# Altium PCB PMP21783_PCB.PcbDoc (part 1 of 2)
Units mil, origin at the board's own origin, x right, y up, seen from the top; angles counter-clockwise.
Board outline 4600 x 4035 mil, 2 copper layers (Top Layer, Bottom Layer), stack 62 mil thick; 142 components, 69 nets, 309 pads, 93 vias.
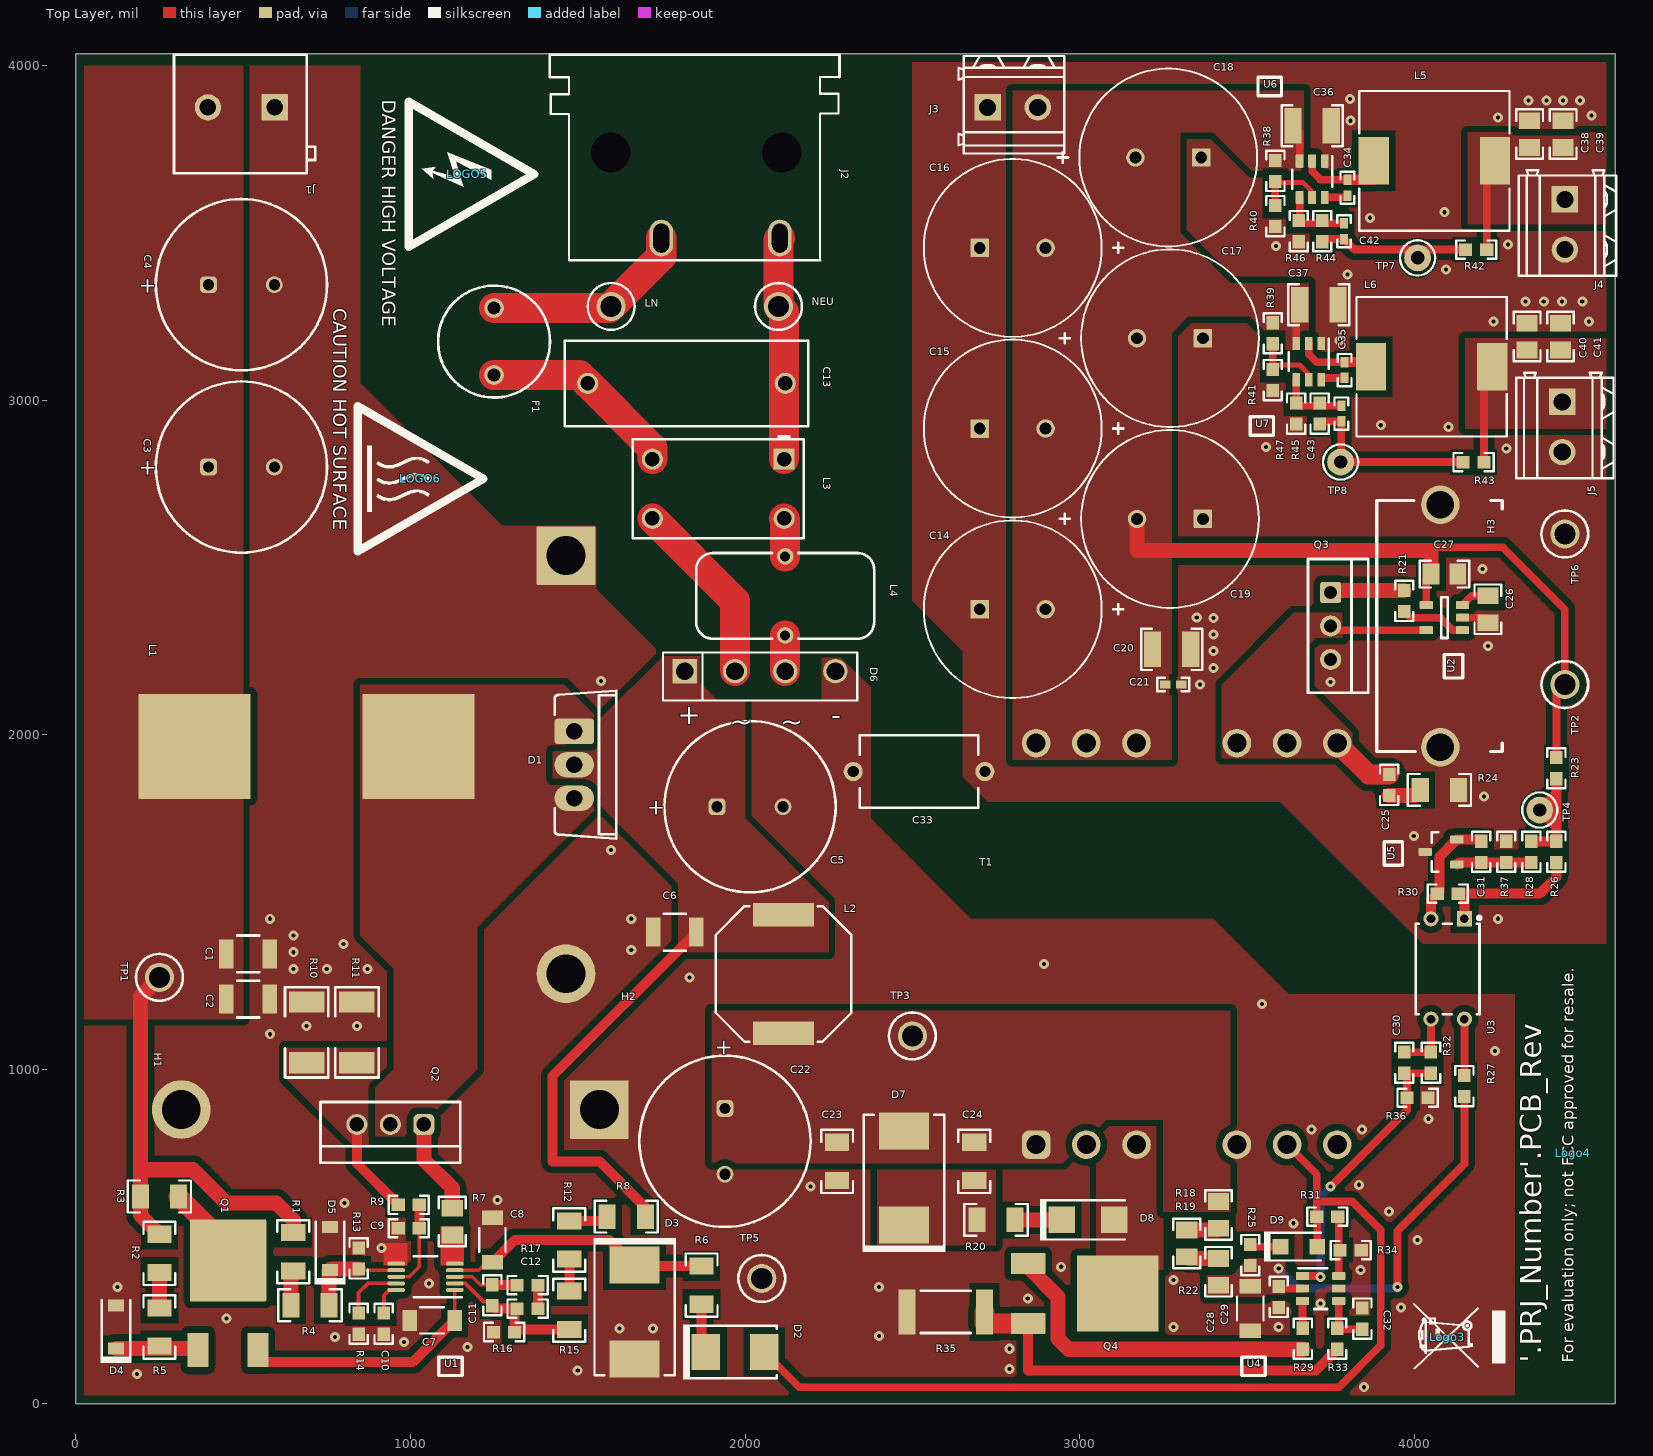
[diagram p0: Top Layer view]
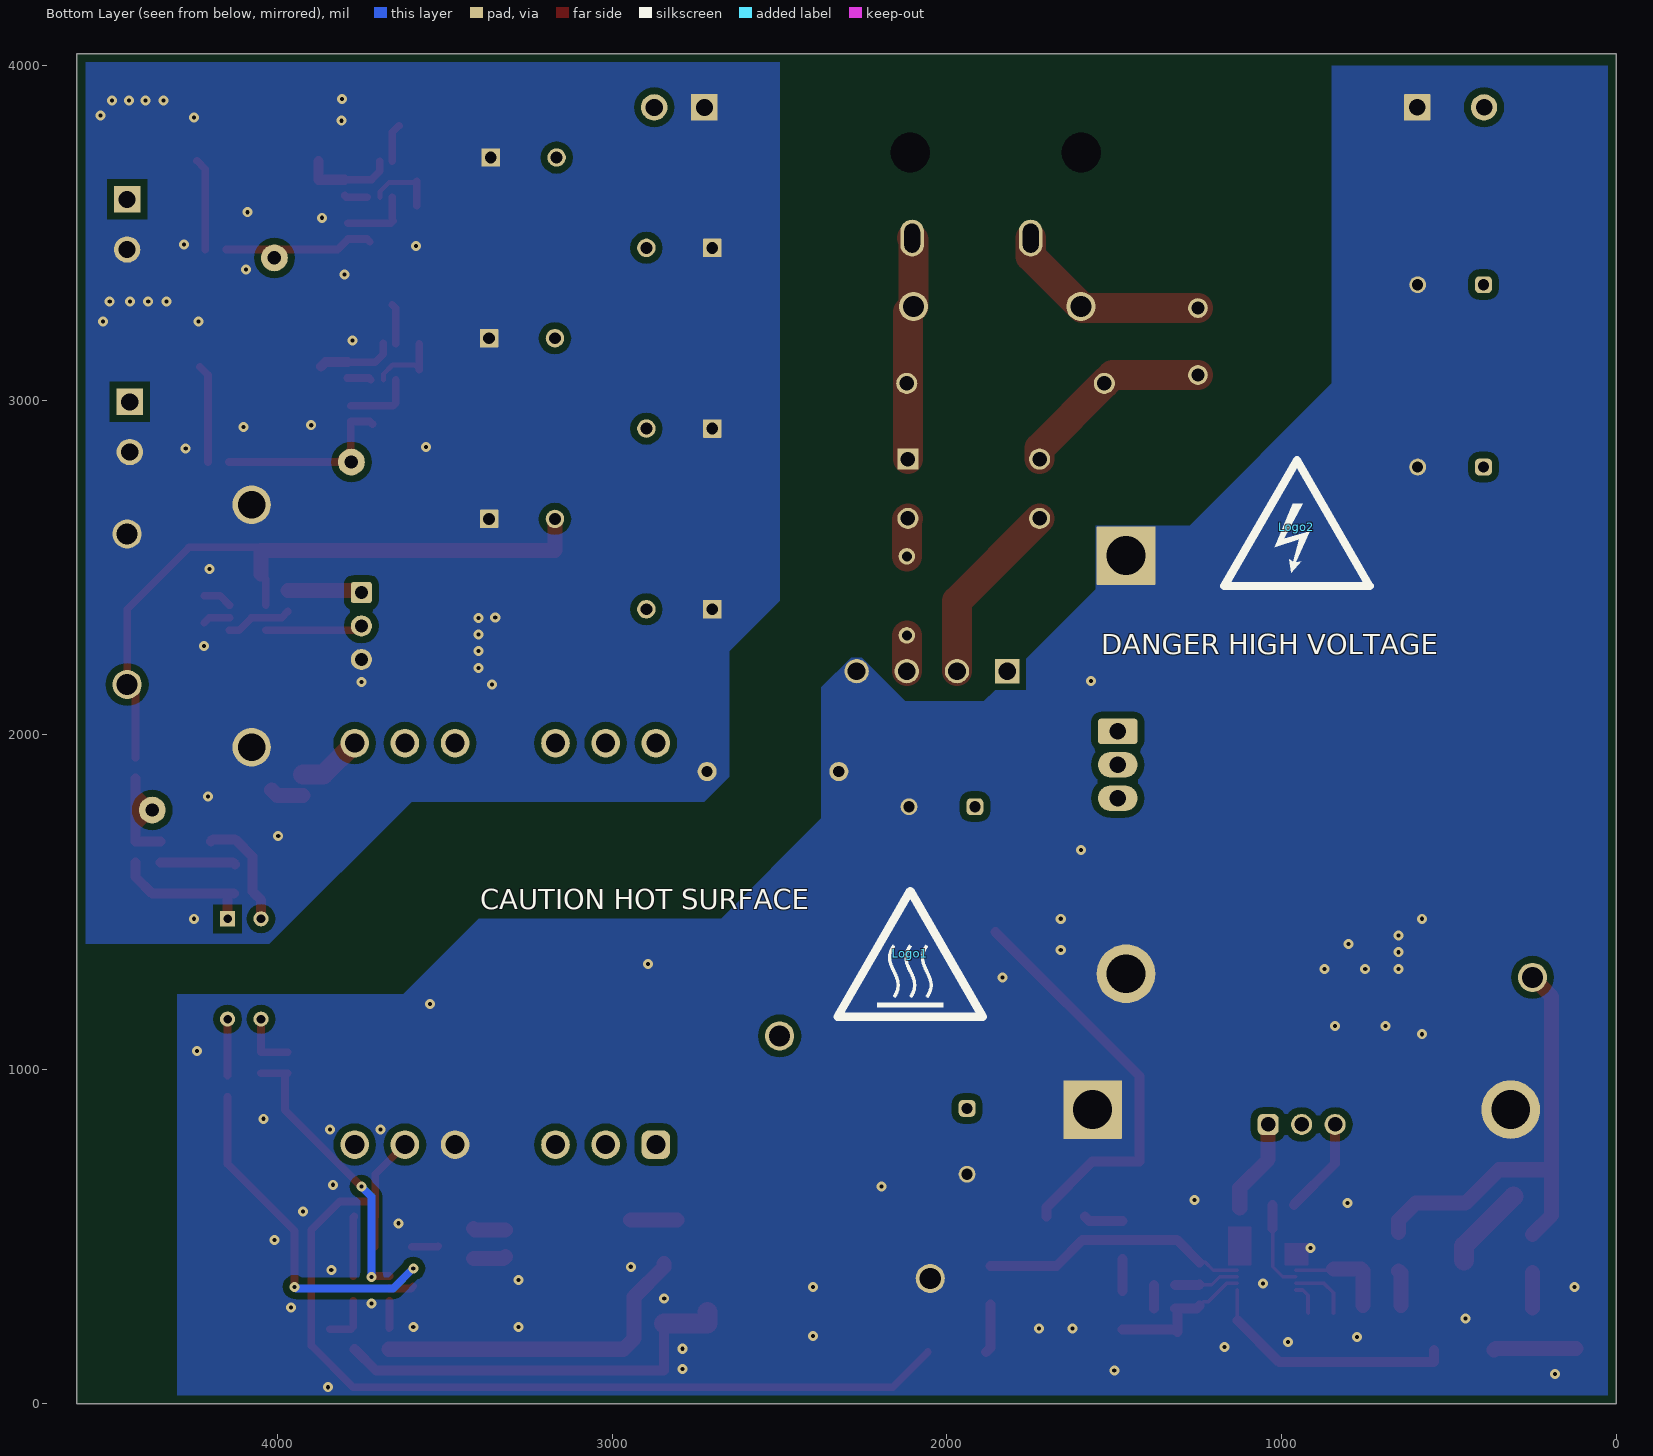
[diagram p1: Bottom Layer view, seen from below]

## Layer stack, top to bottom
Top Solder: solder mask 0.4, Solder Resist, Dk 3.5
Top Layer: signal copper 1.4
Dielectric1: core 59.2, FR-4, Dk 4.8
Bottom Layer: signal copper 1.4
Bottom Solder: solder mask 0.4, Solder Resist, Dk 3.5

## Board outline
0,0 4600,0 4600,4035 0,4035

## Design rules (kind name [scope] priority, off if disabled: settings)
AcuteAngle [All] p1: minimum=4.50000000000000E+0001 checktracksonly=FALSE
AssemblyTestPointUsage [All] p1: valid=2
BoardOutlineClearance BoardOutlineClearance_MountingHoles [OnCopper and InComponentClass('Mounting Holes')] p1: gap=25 ignorepadtopadclearanceinfootprint=FALSE
BoardOutlineClearance BoardOutlineClearance_Poly [OnCopper and InPoly] p2: gap=25 ignorepadtopadclearanceinfootprint=FALSE
BoardOutlineClearance [OnCopper and Not InComponentClass('Logo') and not InComponentClass('FiducialMark') and not InRegion(1000,500,4000,800)] p3: gap=25 ignorepadtopadclearanceinfootprint=FALSE
Clearance Clearance_2 [InNetClass('HV') vs Not InNetClass('HV')] p1: gap=60 ignorepadtopadclearanceinfootprint=FALSE
Clearance Clearance_1 [InNetClass('MV') vs Not InNetClass('MV')] p2: gap=30 ignorepadtopadclearanceinfootprint=FALSE
Clearance Clearance_Keepouts [((IsTrack Or IsArc) And Not InPoly) And IsFree and IsKeepOut vs ((IsTrack Or IsArc) And Not InPoly) And IsFree and IsKeepOut] p3: gap=0 ignorepadtopadclearanceinfootprint=FALSE
Clearance Clearance_BoardEdge_MountingHoles [OnCopper and InComponentClass('Mounting Holes') vs IsKeepOut] p4: gap=40 ignorepadtopadclearanceinfootprint=FALSE except(0: Arc-Hole Track-Hole SMDPad-Hole THPad-Hole Via-Hole Fill-Hole Poly-Hole Region-Hole Text-Hole)
Clearance Clearance_BoardEdge_Poly [OnCopper and InPoly vs IsKeepOut] p5: gap=50 ignorepadtopadclearanceinfootprint=FALSE except(0: Arc-Hole Track-Hole SMDPad-Hole THPad-Hole Via-Hole Fill-Hole Poly-Hole Region-Hole Text-Hole)
Clearance Clearance_BoardEdge [OnCopper and Not InComponentClass('Logo') and not InComponentClass('FiducialMark') and not InRegion(1000,500,4000,800) and Not IsKeepout vs IsKeepOut] p6: gap=50 ignorepadtopadclearanceinfootprint=FALSE
Clearance Clearance_Poly [InPolygon] p7: gap=20 ignorepadtopadclearanceinfootprint=FALSE except(0: Arc-Hole Track-Hole SMDPad-Hole THPad-Hole Via-Hole Fill-Hole Poly-Hole Region-Hole Text-Hole)
Clearance [All] p8: gap=7.87 ignorepadtopadclearanceinfootprint=FALSE except(0: Arc-Hole Track-Hole SMDPad-Hole THPad-Hole Via-Hole Fill-Hole Poly-Hole Region-Hole Text-Hole)
ComponentClearance ComponentClearance_MountingHoles_FiducialMarks [InComponentClass('Mounting Holes') vs InComponentClass('FiducialMark')] p1: gap=20 collisioncheckmode=3 verticalgap=10 showdistances=FALSE
ComponentClearance ComponentClearance_Shunt [InComponentClass('Header') vs InComponentClass('Shunt')] p2: gap=0 collisioncheckmode=3 verticalgap=0 showdistances=FALSE
ComponentClearance ComponentClearance_Logo [InComponentClass('Logo')] p3: gap=5 collisioncheckmode=3 verticalgap=10 showdistances=FALSE
ComponentClearance ComponentClearance_ScrewToNut [(HasFootprint('NY PMS 440 0025 PH')) vs (HasFootprint('Keystone_1902C'))] p4: gap=20 collisioncheckmode=3 verticalgap=100000 showdistances=FALSE
ComponentClearance ComponentClearance_MountingHoles [InComponentClass('Mounting Holes')] p5: gap=20 collisioncheckmode=3 verticalgap=10 showdistances=FALSE
ComponentClearance ComponentClearance_SmallPassives [HasFootprint('0201*') or HasFootprint('0402*') or HasFootprint('0508') or HasFootprint('0603*') or HasFootprint('0612') or HasFootprint('0805*') or HasFootprint('0815*') or HasFootprint('0830*') or HasFootprint('1206*') or HasFootprint('1210*') or HasFootprint('1808*') or HasFootprint('1812*') or HasFootprint('1825*') or HasFootprint('2010*') or HasFootprint('2220*') or HasFootprint('2225*') or HasFootprint('2512*') or HasFootprint('2728*') or HasFootprint('3518*') vs HasFootprint('0201*') or HasFootprint('0402*') or HasFootprint('0508') or HasFootprint('0603*') or HasFootprint('0612') or HasFootprint('0805*') or HasFootprint('0815*') or HasFootprint('0830*') or HasFootprint('1206*') or HasFootprint('1210*') or HasFootprint('1808*') or HasFootprint('1812*') or HasFootprint('1825*') or HasFootprint('2010*') or HasFootprint('2220*') or HasFootprint('2225*') or HasFootprint('2512*') or HasFootprint('2728*') or HasFootprint('3518*')] p6: gap=20 collisioncheckmode=3 verticalgap=20 showdistances=FALSE
ComponentClearance ComponentClearance_THtoSMT [IsThruComponent vs IsSMTComponent] p7: gap=10 collisioncheckmode=3 verticalgap=10 showdistances=FALSE
ComponentClearance ComponentClearance_THtoTH [IsThruComponent vs IsThruComponent] p8: gap=10 collisioncheckmode=3 verticalgap=10 showdistances=FALSE
ComponentClearance [All] p9: gap=10 collisioncheckmode=3 verticalgap=10 showdistances=FALSE
DiffPairsRouting [All] p1: maxlimit=100 minlimit=10 mostfreqgap=10 toplayer_minwidth=15 toplayer_maxwidth=15 toplayer_prefwidth=15 bottomlayer_minwidth=15 bottomlayer_maxwidth=15 bottomlayer_prefwidth=15 maxuncoupledlength=1000
FabricationTestPointUsage TestPointUsage [All] p1: valid=2 allowmultiple=FALSE
FabricationTestpoint Testpoint [All] p1: side=3 testpointundercomponent=TRUE minsize=40 maxsize=100 preferedsize=60 minholesize=0 maxholesize=40 preferedholesize=32 testpointgrid=1 allowsidetop=TRUE allowsidebottom=TRUE usegrid=TRUE gridtolerance=0.01
FanoutControl Fanout_LCC [IsLCC] p1: bgadir=Out bgaviamode=Centered fanoutstyle=Auto fanoutdirection=Alternating viagrid=1 // Fanout_LCC (Default Rule)
FanoutControl Fanout_BGA [IsBGA] p2: bgadir=Out bgaviamode=Centered fanoutstyle=Auto fanoutdirection=Alternating viagrid=1 // Fanout_BGA (Default Rule)
FanoutControl Fanout_Default [All] p4: bgadir=Out bgaviamode=Centered fanoutstyle=Auto fanoutdirection=Alternating viagrid=1 // Fanout_Default (Default Rule)
FanoutControl Fanout_Small [(CompPinCount < 5)] p5: bgadir=Out bgaviamode=Centered fanoutstyle=Auto fanoutdirection=OutThenIn viagrid=1 // Fanout_Small (Default Rule)
Height [All] p1: minheight=0 maxheight=3000 prefheight=500
HoleSize [All] p1: absolutevalues=TRUE maxlimit=251 minlimit=7.87 maxpercent=80.000 minpercent=20.000
MinimumAnnularRing MinimumAnnularRing_ThermalPadVias [IsVia and InAnyComponent] p1: minimumring=5.91
MinimumAnnularRing [All] p2: minimumring=8
MinimumSolderMaskSliver MinimumSolderMaskSliver_Logo [InComponentClass('Logo') vs InComponentClass('Logo')] p1: minsoldermaskwidth=0.7
MinimumSolderMaskSliver [All] p2: minsoldermaskwidth=3.94
PlaneConnect [All] p1: planeconnectstyle=Direct reliefexpansion=10 reliefentries=4 reliefconductorwidth=10 reliefairgap=10
PolygonConnect PolygonConnect_15 [All vs IsNamedPolygon('C109_2') Or  IsNamedPolygon('C107_2') Or  IsNamedPolygon('HV') Or  IsNamedPolygon('Q203_5') Or  IsNamedPolygon('C107_2') Or  IsNamedPolygon('HS') Or  IsNamedPolygon('Q201_5') Or  IsNamedPolygon('Q203_5') Or  IsNamedPolygon('C106_2') Or  IsNamedPolygon('C108_2') Or  IsNamedPolygon('Vout') Or  IsNamedPolygon('Q203_5') Or  IsNamedPolygon('C108_2') Or  IsNamedPolygon('C113_2') Or  IsNamedPolygon('Q203_5') Or  IsNamedPolygon('Q201_5') Or  IsNamedPolygon('C107_2') Or  IsNamedPolygon('C102_1') Or  IsNamedPolygon('SGND') Or  IsNamedPolygon('GND') Or  IsNamedPolygon('SGND') Or  IsNamedPolygon('GND') Or  IsNamedPolygon('IN+') Or  IsNamedPolygon('IN+') Or  IsNamedPolygon('Q201_5') Or  IsNamedPolygon('Q201_5') Or  IsNamedPolygon('SGND') Or  IsNamedPolygon('SGND') Or  IsNamedPolygon('Vout') Or  IsNamedPolygon('Vout') Or  IsNamedPolygon('IN+') Or  IsNamedPolygon('GND') Or  IsNamedPolygon('IN+') Or  IsNamedPolygon('GND')] p1: connectstyle=Direct reliefconductorwidth=10 reliefentries=4 polygonreliefangle="90 Angle" airgapwidth=10
PolygonConnect PolygonConnect_14 [All vs IsNamedPolygon('C106_2') Or  IsNamedPolygon('C107_2') Or  IsNamedPolygon('C107_2') Or  IsNamedPolygon('C107_2') Or  IsNamedPolygon('C102_1') Or  IsNamedPolygon('Q203_5') Or  IsNamedPolygon('Vout') Or  IsNamedPolygon('Q203_5') Or  IsNamedPolygon('Q203_5') Or  IsNamedPolygon('Q201_5') Or  IsNamedPolygon('C108_2') Or  IsNamedPolygon('Q203_5') Or  IsNamedPolygon('HS') Or  IsNamedPolygon('HV') Or  IsNamedPolygon('C108_2') Or  IsNamedPolygon('Q201_5') Or  IsNamedPolygon('C109_2') Or  IsNamedPolygon('Q201_5') Or  IsNamedPolygon('Q201_5') Or  IsNamedPolygon('C113_2')] p2: connectstyle=Direct reliefconductorwidth=10 reliefentries=4 polygonreliefangle="90 Angle" airgapwidth=10
PolygonConnect PolygonConnect_13 [All vs IsNamedPolygon('C102_1') Or  IsNamedPolygon('HV') Or  IsNamedPolygon('C107_2') Or  IsNamedPolygon('C109_2') Or  IsNamedPolygon('C107_2') Or  IsNamedPolygon('C108_2') Or  IsNamedPolygon('C106_2') Or  IsNamedPolygon('C108_2') Or  IsNamedPolygon('C113_2') Or  IsNamedPolygon('C107_2')] p3: connectstyle=Direct reliefconductorwidth=10 reliefentries=4 polygonreliefangle="90 Angle" airgapwidth=10
PolygonConnect PolygonConnect_12 [All vs IsNamedPolygon('C107_2') Or  IsNamedPolygon('C113_2') Or  IsNamedPolygon('C106_2') Or  IsNamedPolygon('C107_2') Or  IsNamedPolygon('C107_2') Or  IsNamedPolygon('C102_1')] p4: connectstyle=Direct reliefconductorwidth=10 reliefentries=4 polygonreliefangle="90 Angle" airgapwidth=10
PolygonConnect PolygonConnect_11 [All vs IsNamedPolygon('C106_2') Or  IsNamedPolygon('C102_1') Or  IsNamedPolygon('C107_2') Or  IsNamedPolygon('C107_2') Or  IsNamedPolygon('C107_2')] p5: connectstyle=Direct reliefconductorwidth=10 reliefentries=4 polygonreliefangle="90 Angle" airgapwidth=10
PolygonConnect PolygonConnect_10 [All vs IsNamedPolygon('C106_2')] p6: connectstyle=Direct reliefconductorwidth=10 reliefentries=4 polygonreliefangle="90 Angle" airgapwidth=10
PolygonConnect PolygonConnect_9 [All vs IsNamedPolygon('C11_1') Or  IsNamedPolygon('Vin') Or  IsNamedPolygon('Vin') Or  IsNamedPolygon('5V') Or  IsNamedPolygon('D6_2') Or  IsNamedPolygon('Q3_3') Or  IsNamedPolygon('GND2') Or  IsNamedPolygon('GND2') Or  IsNamedPolygon('GND') Or  IsNamedPolygon('Q3_4') Or  IsNamedPolygon('12V5') Or  IsNamedPolygon('GND') Or  IsNamedPolygon('12V5') Or  IsNamedPolygon('D3_1')] p7: connectstyle=Direct reliefconductorwidth=10 reliefentries=4 polygonreliefangle="90 Angle" airgapwidth=10
PolygonConnect PolygonConnect_8 [All vs IsNamedPolygon('C11_1') Or  IsNamedPolygon('Vin') Or  IsNamedPolygon('12V5') Or  IsNamedPolygon('Q3_3') Or  IsNamedPolygon('GND2') Or  IsNamedPolygon('GND2') Or  IsNamedPolygon('5V') Or  IsNamedPolygon('Q3_4') Or  IsNamedPolygon('12V5')] p8: connectstyle=Direct reliefconductorwidth=10 reliefentries=4 polygonreliefangle="90 Angle" airgapwidth=10
PolygonConnect PolygonConnect_7 [All vs IsNamedPolygon('GND2') Or  IsNamedPolygon('GND2') Or  IsNamedPolygon('5V') Or  IsNamedPolygon('12V5') Or  IsNamedPolygon('12V5') Or  IsNamedPolygon('C11_1')] p9: connectstyle=Direct reliefconductorwidth=10 reliefentries=4 polygonreliefangle="90 Angle" airgapwidth=10
PolygonConnect PolygonConnect_6 [All vs IsNamedPolygon('GND2') Or  IsNamedPolygon('SGND') Or  IsNamedPolygon('GND1') Or  IsNamedPolygon('C901_1') Or  IsNamedPolygon('SGND') Or  IsNamedPolygon('GND2') Or  IsNamedPolygon('GND1')] p10: connectstyle=Direct reliefconductorwidth=10 reliefentries=4 polygonreliefangle="90 Angle" airgapwidth=10
PolygonConnect PolygonConnect_5 [All vs IsNamedPolygon('GND1') Or  IsNamedPolygon('GND1')] p11: connectstyle=Direct reliefconductorwidth=10 reliefentries=4 polygonreliefangle="90 Angle" airgapwidth=10
PolygonConnect PolygonConnect_4 [All vs IsNamedPolygon('C21_1') Or  IsNamedPolygon('C5_1') Or  IsNamedPolygon('C12_2') Or  IsNamedPolygon('C2_2') Or  IsNamedPolygon('C13_1') Or  IsNamedPolygon('C28_1') Or  IsNamedPolygon('C6_1') Or  IsNamedPolygon('GND') Or  IsNamedPolygon('GND2') Or  IsNamedPolygon('C14_1') Or  IsNamedPolygon('C13_1') Or  IsNamedPolygon('Q1_3') Or  IsNamedPolygon('C14_1') Or  IsNamedPolygon('C5_1') Or  IsNamedPolygon('GND2') Or  IsNamedPolygon('C28_1') Or  IsNamedPolygon('D5_2') Or  IsNamedPolygon('D6_2') Or  IsNamedPolygon('D2_1') Or  IsNamedPolygon('C12_2') Or  IsNamedPolygon('D2_1') Or  IsNamedPolygon('C4_1') Or  IsNamedPolygon('C4_1') Or  IsNamedPolygon('C2_2') Or  IsNamedPolygon('GND') Or  IsNamedPolygon('C33_1') Or  IsNamedPolygon('C9_1')] p12: connectstyle=Direct reliefconductorwidth=10 reliefentries=4 polygonreliefangle="90 Angle" airgapwidth=10
PolygonConnect PolygonConnect_3 [All vs IsNamedPolygon('C28_1') Or  IsNamedPolygon('C12_2') Or  IsNamedPolygon('C28_1') Or  IsNamedPolygon('C9_1') Or  IsNamedPolygon('D5_2') Or  IsNamedPolygon('C12_2') Or  IsNamedPolygon('C2_2') Or  IsNamedPolygon('C14_1') Or  IsNamedPolygon('C4_1') Or  IsNamedPolygon('C14_1') Or  IsNamedPolygon('D6_2') Or  IsNamedPolygon('GND2') Or  IsNamedPolygon('Q1_3') Or  IsNamedPolygon('C5_1') Or  IsNamedPolygon('D2_1') Or  IsNamedPolygon('C4_1') Or  IsNamedPolygon('C13_1') Or  IsNamedPolygon('C5_1') Or  IsNamedPolygon('C13_1') Or  IsNamedPolygon('C33_1') Or  IsNamedPolygon('D2_1') Or  IsNamedPolygon('GND') Or  IsNamedPolygon('GND') Or  IsNamedPolygon('GND2') Or  IsNamedPolygon('C2_2') Or  IsNamedPolygon('C6_1') Or  IsNamedPolygon('C21_1')] p13: connectstyle=Direct reliefconductorwidth=10 reliefentries=4 polygonreliefangle="90 Angle" airgapwidth=10
PolygonConnect PolygonConnect_2 [All vs IsNamedPolygon('C21_1') Or  IsNamedPolygon('C4_1') Or  IsNamedPolygon('D5_2') Or  IsNamedPolygon('C5_1') Or  IsNamedPolygon('C14_1') Or  IsNamedPolygon('C13_1') Or  IsNamedPolygon('C4_1') Or  IsNamedPolygon('C33_1') Or  IsNamedPolygon('C12_2') Or  IsNamedPolygon('D2_1') Or  IsNamedPolygon('C2_2') Or  IsNamedPolygon('C28_1') Or  IsNamedPolygon('C12_2') Or  IsNamedPolygon('D2_1') Or  IsNamedPolygon('C5_1') Or  IsNamedPolygon('Q1_3') Or  IsNamedPolygon('GND') Or  IsNamedPolygon('D6_2') Or  IsNamedPolygon('C6_1') Or  IsNamedPolygon('C2_2') Or  IsNamedPolygon('C14_1') Or  IsNamedPolygon('C28_1') Or  IsNamedPolygon('C13_1') Or  IsNamedPolygon('C9_1') Or  IsNamedPolygon('GND')] p14: connectstyle=Direct reliefconductorwidth=10 reliefentries=4 polygonreliefangle="90 Angle" airgapwidth=10
PolygonConnect PolygonConnect_1 [All vs IsNamedPolygon('C28_1') Or  IsNamedPolygon('D5_2') Or  IsNamedPolygon('C5_1') Or  IsNamedPolygon('C5_1') Or  IsNamedPolygon('D2_1') Or  IsNamedPolygon('C21_1') Or  IsNamedPolygon('C9_1') Or  IsNamedPolygon('C4_1') Or  IsNamedPolygon('C14_1') Or  IsNamedPolygon('C28_1') Or  IsNamedPolygon('C6_1') Or  IsNamedPolygon('C12_2') Or  IsNamedPolygon('C33_1') Or  IsNamedPolygon('C4_1') Or  IsNamedPolygon('C13_1') Or  IsNamedPolygon('C12_2') Or  IsNamedPolygon('D6_2') Or  IsNamedPolygon('C2_2') Or  IsNamedPolygon('C14_1') Or  IsNamedPolygon('D2_1') Or  IsNamedPolygon('C2_2') Or  IsNamedPolygon('C13_1')] p15: connectstyle=Direct reliefconductorwidth=10 reliefentries=4 polygonreliefangle="90 Angle" airgapwidth=10
PolygonConnect [All] p16: connectstyle=Direct reliefconductorwidth=10 reliefentries=4 polygonreliefangle="90 Angle" airgapwidth=10
RoutingVias ThermalPadVias [IsVia and InAnyComponent] p1: holewidth=7.87 width=19.68 viastyle="Through Hole" minholewidth=7.87 minwidth=19.68 maxholewidth=12.99 maxwidth=23.62
RoutingVias [All] p2: holewidth=16 width=34 viastyle="Through Hole" minholewidth=7.87 minwidth=20 maxholewidth=40 maxwidth=65
SilkToBoardRegionClearance [Not ((IsComment or IsDesignator) And (Hide <> 'False')) and not InRegion(1000,500,4000,800)] p1:
SilkToSilkClearance SilkToSilkClearance_Pb-FreeLogo [(HasFootprint('Pb-Free_Overlay_Medium') OR HasFootprint('Pb-Free_Overlay_Small')) vs (HasFootprint('Pb-Free_Overlay_Medium') OR HasFootprint('Pb-Free_Overlay_Small'))] p1: silktosilkclearance=0
SilkToSilkClearance [All] p2: silktosilkclearance=4
SilkToSolderMaskClearance SilkToComponentPadClearance [IsPad and InAnycomponent] p1: minsilkscreentomaskgap=5 clearancetoexposedcopper=TRUE
SilkToSolderMaskClearance "Silk to Solder Mask Opening" [All] p2: minsilkscreentomaskgap=4 clearancetoexposedcopper=FALSE
SolderMaskExpansion [All] p1: expansion=1.97
Width [All] p1: maxlimit=100 minlimit=6 preferedwidth=10 checkconnectedcopper=TRUE
14 further rules are at their usual default settings.

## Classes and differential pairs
component class "PMP21783_SCH 2": C14 C15 C16 C17 C18 C19 C20 C21 C22 C23 C24 C25 C26 C27 C28 C29 C30 C31 C32 C33 C34 C35 C36 C37 C38 C39 C40 C41 C42 C43 D7 D8 D9 H3 J3 J4 J5 L5 L6 LOGO5 LOGO6 Q3 Q4 R18 R19 R20 R21 R22 R23 R24 R25 R26 R27 R28 R29 R30 R31 R32 R33 R34 R35 R36 R37 R38 R39 R40 R41 R42 R43 R44 R45 R46 R47 R48 T1 TP2 TP3 TP4 TP5 TP6 TP7 TP8 U2 U3 U4 U5 U6 U7
component class "PMP21783_SCH 1": C1 C2 C3 C4 C5 C6 C7 C8 C9 C10 C11 C12 C13 D1 D2 D3 D4 D5 D6 F1 H1 H2 J1 J2 L1 L2 L3 L4 LN Logo1 Logo2 Logo3 Logo4 NEU Q1 Q2 R1 R2 R3 R4 R5 R6 R7 R8 R9 R10 R11 R12 R13 R14 R15 R16 R17 TP1 U1

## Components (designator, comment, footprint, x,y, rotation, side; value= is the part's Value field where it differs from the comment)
C1 "C1210C104KBRAC7800" 1210_280 515,1345 r0 top value=0.1uF
C2 "C1210C104KBRAC7800" 1210_280 515,1210 r0 top value=0.1uF
C3 "450BXW47MEFC12.5X35" BXW_1250x3500 495,2800 r0 top value=47uF
C4 "450BXW47MEFC12.5X35" BXW_1250x3500 495,3345 r0 top value=47uF
C5 "450BXW47MEFC12.5X35" BXW_1250x3500 2015,1785 r0 top value=47uF
C6 "C1210C104KBRAC7800" 1210_280 1790,1410 r180 top value=0.1uF
C7 "GRM31CR71H475KA12L" 1206_180 1065,250 r180 top value=4.7uF
C8 "EMK316BB7226ML-T" 1206_190 1245,490 r90 top value=22uF
C9 "GRM188R71H271KA01D" 0603 995,525 r180 top value=270pF
C10 "GRM188R71H103KA01D" 0603 920,240 r270 top value=0.01uF
C11 "GRM188R71E222KA01D" 0603 1245,325 r90 top value=2200pF
C12 "GRM188R71E474KA12D" 0603 1350,285 r0 top value=0.47uF
C13 "890324025017" WCAP-FTX2_1800x600x1200 1825,3050 r0 top value=0.1uF
C14 "860080578019" FP-860080578019_RADIAL-MFG 2800,2375 r0 top
C15 "860080578019" FP-860080578019_RADIAL-MFG 2800,2915 r0 top
C16 "860080578019" FP-860080578019_RADIAL-MFG 2800,3455 r0 top
C17 "860080578019" FP-860080578019_RADIAL-MFG 3270,3185 r180 top
C18 "860080578019" FP-860080578019_RADIAL-MFG 3265,3725 r180 top
C19 "860080578019" FP-860080578019_RADIAL-MFG 3270,2645 r180 top
C20 "GRM32DR71E106KA12L" 1210_220 3275,2255 r0 top value=10uF
C21 "GRM155R71E104KE14D" 0402 3280,2150 r0 top value=0.1uF
C22 "450BXW47MEFC12.5X35" BXW_1250x3500 1940,785 r270 top value=47uF
C23 "VJ1206Y473KXEAT5Z" 1206 2275,725 r270 top value=0.047uF
C24 "12061C102JAT2A" 1206 2685,725 r270 top value=1000pF
C25 "GRM188R72A222KA01D" 0603 3925,1850 r90 top value=2200pF
C26 "C0805C225K4RACTU" 0805_HV 4220,2375 r270 top value=2.2uF
C27 "GCM21BR71H105KA03K" 0805_HV 4090,2480 r0 top value=1uF
C28 "CGA5L1X7R1H106K160AC" 1206_190 3510,285 r270 top value=10uF
C29 "C1608X7R1E104K080AA" 0603 3595,320 r90 top value=0.1uF
C30 "GRM188R71C473KA01D" 0603 3970,1020 r270 top value=0.047uF
C31 "GRM188R71E153KA01D" 0603 4200,1650 r90 top value=0.015uF
C32 "GRM188R71H271KA01D" 0603 3845,255 r90 top value=270pF
C33 "C921U222MVVDBA7317" C900_9x13 2520,1890 r180 top value=2200pF
C34 "GRM155R71E104KE14D" 0402 3800,3635 r90 top value=0.1uF
C35 "GRM155R71E104KE14D" 0402 3792.12,3089.91 r90 top value=0.1uF
C36 "GRM32DR71E106KA12L" 1210_220 3695,3820 r0 top value=10uF
C37 "GRM32DR71E106KA12L" 1210_220 3715,3285 r0 top value=10uF
C38 "GRM21BR61A226ME44L" 0805_HV 4345,3795 r90 top value=22uF
C39 "GRM21BR61A226ME44L" 0805_HV 4445,3795 r90 top value=22uF
C40 "GRM21BR61A226ME44L" 0805_HV 4337.12,3189.91 r90 top value=22uF
C41 "GRM21BR61A226ME44L" 0805_HV 4437.12,3189.91 r90 top value=22uF
C42 "C1005C0G1H680J050BA" 0402 3790,3505 r90 top value=68pF
C43 "C0402C330J5GAC" 0402 3782.12,2959.91 r90 top value=33pF
D1 "MUR1640CTG" TO-220AB 1489.69,1910.32 r270 top locked value=400V
D2 "MURS140-13-F" SMB 1970,155 r0 top value=400V
D3 "SMCJ13A-TR" SMC 1670,275 r270 top value=13V
D4 "MMSZ5263BT1G" SOD-123 120,230 r90 top value=56V
D5 "MMSZ4689T1G" SOD-123 760,465 r90 top value=5.1V
D6 "KBP06G" KBP 2045,2190 r0 top value=600V
D7 "SMCJ200A" SMC 2475,675 r90 top value=200V
D8 "US1M-13-F" SMA 3025,550 r0 top value=1000V
D9 "PMEG10010ELRX" SOD-123W 3655,470 r0 top value=100V
F1 "37216300001" FUSE_372 1250,3175 r90 top
H1 "7020B-MTG" FP-7020B-MTG_HEAT_SINK_TO220-MFG 940,874.69 r180 top
H2 "7020B-MTG" FP-7020B-MTG_HEAT_SINK_TO220-MFG 1470,1910.32 r270 top
H3 "7173DG" HSINK_7173DG 3905,2325 r90 top
J1 "ED120/2DS" On-Shore_ED120_2DS 495,3875 r180 top
J2 "770W-X2/10" CONN_AC_770W-SERIES 1854.09,3614.02 r0 top
J3 "691214310002" Wurth_691214310002 2800,3875 r0 top
J4 "691214310002" Wurth_691214310002 4450,3525 r270 top
J5 "691214310002" Wurth_691214310002 4442.12,2919.91 r270 top
L1 "74437529203221" "WE-HCF Round_2920" 690,1965 r0 top value=220uH
L2 "744065220" WE-TPC-XLH2 2115,1285 r270 top value=22uH
L3 "7448011305" WE-CMBNC_XS 1920,2735 r270 top value=5mH
L4 "7447031" WE-FI_1350x700 2120,2415 r270 top value=140uH
L5 "7443331000" WE-HCC_1090 4060,3715 r0 top value=10uH
L6 "7443331000" WE-HCC_1090 4052.12,3099.91 r0 top value=10uH
LN "5125" Keystone5125 1600,3280 r0 top
Logo1 "CAUTION HOT SURFACE" IEC_HotSurface_Medium 2110,1344.75 r180 bottom (schematic designator LOGO1)
Logo2 "DANGER HIGH VOLTAGE" IEC_HighVoltage_Medium 954,2620 r180 bottom (schematic designator LOGO2)
Logo3 "WEEE logo" WEEE_Minimum 4100,200 r90 top
Logo4 "FCC disclaimer" FCC_disclaimer 4475,750 r90 top
LOGO5 "DANGER HIGH VOLTAGE" IEC_HighVoltage_Medium 1170,3675 r270 top
LOGO6 "CAUTION HOT SURFACE" IEC_HotSurface_Medium 1030,2765 r270 top
NEU "5127" Keystone5127 2100,3280 r0 top
Q1 "AOD3N50" DPAK 455,295 r90 top value=500V
Q2 "IPP410N30NAKSA1" TO-220-3 940,835.32 r180 top value=300V
Q3 "CSD19531KCS" KCS0003B 3750,2325 r0 top value=100V
Q4 "IPD70R360P7SAUMA1" DPAK 2980,330 r0 top value=700V
R1 "CRCW12061M00JNEA" 1206 650,455 r270 top value=1.0Meg
R2 "CRCW1206100KJNEA" 1206 250,450 r90 top value=100k
R3 "CRCW12061K54FKEA" 1206 250,620 r180 top value=1.54k
R4 "CRCW12061M00JNEA" 1206 700,295 r0 top value=1.0Meg
R5 "CRCW1206100KJNEA" 1206 250,230 r90 top value=100k
R6 "RC1206FR-07390RL" 1206 1870,355 r90 top value=390
R7 "MCR10EZPJ000" 0805_HV 1125,545 r90 top value=0
R8 "RC1206FR-0749R9L" 1206 1645,560 r0 top value=49.9
R9 "CRCW06031K00FKEA" 0603 995,595 r180 top value=1.00k
R10 "CSR2010FTR150" 2010 690,1110.32 r270 top value=0.15
R11 "CSR2010FTR150" 2010 840,1110.32 r270 top value=0.15
R12 "CRCW1206590KFKEA" 1206 1475,490 r90 top value=590k
R13 "CRCW0603113KFKEA" 0603 845,435 r270 top value=113k
R14 "CRCW060386K6FKEA" 0603 845,240 r90 top value=86.6k
R15 "CRCW1206590KFKEA" 1206 1475,280 r90 top value=590k
R16 "CRCW060310K0FKEA" 0603 1280,215 r0 top value=10.0k
R17 "CRCW060320K0FKEA" 0603 1350,355 r0 top value=20.0k
R18 "ERJ-6ENF2004V" 0805_HV 3415,565 r90 top value=2.00Meg
R19 "ERJ-6ENF2004V" 0805_HV 3320,480 r90 top value=2.00Meg
R20 "CRCW12060000Z0EA" 1206 2750,550 r180 top value=0
R21 "CRCW06030000Z0EA" 0603 3970,2400 r90 top value=0
R22 "ERJ-6ENF2004V" 0805_HV 3415,395 r90 top value=2.00Meg
R23 "CRCW060349R9FKEA" 0603 4425,1900 r90 top value=49.9
R24 "CRCW12060000Z0EA" 1206 4075,1835 r180 top value=0
R25 "CRCW06031R00JNEA" 0603 3510,445 r270 top value=1.0
R26 "CRCW06032K05FKEA" 0603 4425,1650 r90 top value=2.05k
R27 "CRCW06030000Z0EA" 0603 4150,950 r270 top value=0
R28 "CRCW060395K3FKEA" 0603 4350,1650 r90 top value=95.3k
R29 "CRCW06030000Z0EA" 0603 3667.09,195 r270 top value=0
R30 "CRCW06031K00FKEA" 0603 4100,1525 r0 top value=1.00k
R31 "CRCW0603107KFKEA" 0603 3740,560 r180 top value=107k
R32 "CRCW060332K4FKEA" 0603 4050,1020 r90 top value=32.4k
R33 "CRCW06031K47FKEA" 0603 3770,195 r270 top value=1.47k
R34 "CRCW060322K1FKEA" 0603 3810,460 r180 top value=22.1k
R35 "CSRN2512FKR250" 2512 2600,275 r0 top value=0.25
R36 "CRCW06034K02FKEA" 0603 4010,915 r180 top value=4.02k
R37 "CRCW060311K0FKEA" 0603 4275,1650 r270 top value=11.0k
R38 "CRCW0603511KFKEA" 0603 3585,3685 r90 top value=511k
R39 "CRCW0603511KFKEA" 0603 3577.12,3199.91 r90 top value=511k
R40 "CRCW0603105KFKEA" 0603 3585,3550 r90 top value=105k
R41 "CRCW0603105KFKEA" 0603 3577.12,3059.91 r90 top value=105k
R42 "CRCW060349R9FKEA" 0603 4185,3450 r0 top value=49.9
R43 "CRCW060349R9FKEA" 0603 4177.12,2814.91 r0 top value=49.9
R44 "CRCW0603100KFKEA" 0603 3725,3505 r270 top value=100k
R45 "CRCW0603100KFKEA" 0603 3717.12,2959.91 r270 top value=100k
R46 "CRCW060313K3FKEA" 0603 3655,3505 r90 top value=13.3k
R47 "CRCW060322K1FKEA" 0603 3647.12,2959.91 r90 top value=22.1k
T1 "RTLI-1311" Renco_RTLI-1311 3320,1375 r90 top value=150uH
TP1 "5010" Keystone5010 250,1275 r0 top
TP2 "5010" Keystone5010 4450,2150 r0 top
TP3 "5010" Keystone5010 2500,1100 r0 top
TP4 "5002" Keystone5002 4375,1775 r90 top
TP5 "5011" Keystone5011 2050,375 r0 top
TP6 "5011" Keystone5011 4450,2600 r0 top
TP7 "5002" Keystone5002 4010,3425 r90 top
TP8 "5002" Keystone5002 3780,2815 r90 top
U1 "LM5022MM" DGS0010A_N 1045,380 r180 top
U2 "UCC24612-1DBVR" DBV0005A_N 4090,2350 r180 top
U3 "VO618A-3" DIP-4 4100,1300 r270 top
U4 "UCC28742DBVR" DBV0006A_N 3720,345 r0 top
U5 "TLVH431AQDBZR" DBZ0003A_N 4080,1650 r180 top
U6 "TPS54302DDCR" DDC0006A_N 3695,3660 r270 top
U7 "TPS54302DDCR" DDC0006A_N 3684.65,3114.91 r270 top

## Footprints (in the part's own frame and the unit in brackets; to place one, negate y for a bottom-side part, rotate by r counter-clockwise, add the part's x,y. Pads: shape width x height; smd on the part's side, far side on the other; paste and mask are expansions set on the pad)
0402 [mm] "0402 from SM-752 data"
  rect 0.8x0.6 smd: 1(-0.6,0) 2(0.6,0)
  silkscreen extent -1.22,-0.52 1.22,0.52, body extent -0.55,-0.3 0.55,0.3, height 0.6
0603 [mm] "0603 from SM-752 data"
  rect 1x0.95 smd: 1(-0.8,0) 2(0.8,0)
  silkscreen extent -1.52,-0.69 1.52,0.69, body extent -0.87,-0.47 0.87,0.47, height 1
0805_HV [mil] "0805 with 30mil clearance between pads"
  rect 50x63 smd: 1(-40,0) 2(40,0)
  silkscreen extent -74,-40 74,40, body extent -43,-29 43,29, height 57
1206 [mm] "1206 from SM-752 data"
  rect 1.3x1.85 smd: 1(-1.45,0) 2(1.45,0)
  silkscreen extent -2.4,-1.21 2.4,1.21, body extent -1.7,-0.9 1.7,0.9, height 1.35
1206_180 [mm] "1206_180"
  rect 1.1x1.6 smd: 1(-1.7,0) 2(1.7,0)
  silkscreen extent -0.9,-1 0.9,1, body extent -1.75,-0.95 1.75,0.95, height 1.8
1206_190 [mm] "1206_190"
  rect 1.1x1.6 smd: 1(-1.7,0) 2(1.7,0)
  silkscreen extent -0.9,-1 0.9,1, body extent -1.75,-0.95 1.75,0.95, height 1.9
1210_220 [mm] "1210"
  rect 1.3x2.7 smd: 1(-1.45,0) 2(1.45,0)
  silkscreen extent -2.32,-1.57 2.32,1.57, body extent -1.7,-1.35 1.7,1.35, height 2.2
1210_280 [mm] "SMD, 2-Leads, Body 3.6x2.8mm, Height 2.8mm"
  rect 1.1x2.2 smd: 1(-1.65,0) 2(1.65,0)
  silkscreen extent -0.84,-1.4 0.84,1.4, body extent -1.8,-1.4 1.8,1.4, height 2.8
2010 [mm] "Chip Capacitor, Body 5.08x2.54mm, IPC Medium Density"
  rect 1.6x2.7 smd: 1(-2.3,0) 2(2.3,0)
  silkscreen extent -3.42,-1.65 3.42,1.65, body extent -2.73,-1.45 2.73,1.45, height 1.66
2512 [mm] "Chip Resistor, Body 6.3x3.2mm, IPC Medium Density"
  rect 1.3x3.4 smd: 1(-2.95,0) 2(2.95,0)
  silkscreen extent -1.9,-1.6 1.9,1.6, body extent -3.22,-1.67 3.22,1.67, height 0.71
BXW_1250x3500 [mm] "TH, 2-Leads, Dia 12.5mm, Pin Spacing 5mm"
  rrect50% 1.275x1.275 hole 0.85: 1(-2.5,0)
  round 1.275 hole 0.85: 2(2.5,0)
  silkscreen extent -6.5,-6.5 6.5,6.5, body extent -6.5,-6.5 6.51,6.5, height 37.01
C900_9x13 [mm] "Kemet"
  round 1.45 hole 0.85: 1(-5,0) 2(5,0)
  silkscreen extent -4.5,-2.75 4.5,2.75, body extent -4.49,-2.75 4.49,2.75, height 12.96
CONN_AC_770W-SERIES [mm] "Qualtek Electronics"
  oval 1.8x2.8 hole 1.2 slot 2.2 at 90 deg: 1(6.35,-3.3) 2(-2.65,-3.3)
  round 2 hole 3 unplated: MH1(6.5,3.2) MH2(-6.5,3.2)
  silkscreen extent -11.12,-4.97 10.87,10.63, body extent -11.05,-4.8 10.8,10.6, height 22
DBV0005A_N [mm] "SOT23, 5-Leads, Body 2.9x1.6mm, Pitch 0.95mm, Lead Span 2.8mm, IPC Medium Density"
  rrect17% 1x0.6 smd: 1(-1.375,0.95) 2(-1.375,0) 3(-1.375,-0.95) 4(1.375,-0.95) 5(1.375,0.95)
  silkscreen extent -0.25,-1.55 0.25,1.55, body extent -1.42,-1.46 1.42,1.46, height 1.09
DBV0006A_N [mm] "SOT23, 6-Leads, Body 2.9x1.6mm, Pitch 0.95mm, Lead Span 2.8mm, IPC Medium Density"
  rrect17% 1x0.6 smd: 1(-1.375,0.95) 2(-1.375,0) 3(-1.375,-0.95) 4(1.375,-0.95) 5(1.375,0) 6(1.375,0.95)
  silkscreen extent -1.68,-1.55 0.5,1.55, body extent -1.42,-1.46 1.42,1.46, height 1.12
DBZ0003A_N [mm] "SOT23, 3-Leads, Body 2.9x1.3mm, Pitch 0.95mm, Lead Span 2.4mm, IPC Medium Density"
  rrect17% 1x0.6 smd: 1(-1.2,0.95) 2(-1.2,-0.95) 3(1.2,0)
  silkscreen extent 0.2,-1.5 0.7,1.5, body extent -1.26,-1.46 1.26,1.46, height 0.98
DDC0006A_N [mm]
  rrect17% 1x0.6 smd: 1(-1.375,0.95) 2(-1.375,0) 3(-1.375,-0.95) 4(1.375,-0.95) 5(1.375,0) 6(1.375,0.95)
  silkscreen extent -1.75,-1.52 0.7,1.53, body extent -1.43,-1.48 1.43,1.49, height 0.92
DGS0010A_N [mm] "TSSOP, 10-Leads, Body 3x3mm, Pitch 0.5mm, IPC Medium Density"
  oval 1.35x0.3 smd: 1(-2.225,1) 2(-2.225,0.5) 3(-2.225,0) 4(-2.225,-0.5) 5(-2.225,-1) 6(2.225,-1) 7(2.225,-0.5) 8(2.225,0) 9(2.225,0.5) 10(2.225,1)
  silkscreen extent -2.75,-1.55 0.9,1.55, body extent -2.45,-1.5 2.45,1.5, height 0.96
DIP-4 [mm] "DIP, 4-Leads, Body 6.86x4.83mm, Pitch 2.54mm"
  rect 1.15x1.15 hole 0.65: 1(-3.81,1.27)
  round 1.15 hole 0.65: 2(-3.81,-1.27) 3(3.81,-1.27) 4(3.81,1.27)
  silkscreen extent -4,-2.41 3.43,2.52, body extent -4.02,-2.41 4.02,2.41, height 5.59
DPAK [mm] "D-PAK, 3-Pads, Body 6.22x6.73mm (max), TO-252AA using nominal STEP model"
  rrect6% 2.6x1.6 smd: 1(-3.4,2.28) 3(-3.4,-2.28)
  rrect2% 6.2x5.8 smd paste-3: 2(3.4,0)
  body extent -3.86,-3.29 5.84,3.29, height 2.48
FCC_disclaimer [mil]
FP-7020B-MTG_HEAT_SINK_TO220-MFG [mm]
  rrect2% 4.45x4.45 hole 2.95 paste-1000 mask+0: 1(-15.87,-0.13)
  round 4.45 hole 2.95 paste-1000 mask+0: 2(15.87,-0.13)
  body extent -18.2,-6.07 18.2,6.07, height 0.25
FP-860080578019_RADIAL-MFG [mm]
  rrect7% 1.4x1.4 hole 0.9 paste-1000 mask+0: 1(-2.5,0)
  round 1.4 hole 0.9 paste-1000 mask+0: 2(2.5,0)
  silkscreen extent -6.75,-6.75 8.38,6.75, body extent -6.85,-6.85 6.85,6.85, height 0.25
FUSE_372 [mm] "LITTELFUSE"
  round 1.5 hole 1: 1(-2.54,0) 2(2.54,0)
  silkscreen extent -4.25,-4.25 4.25,4.25, body extent -4.25,-4.25 4.25,4.25, height 8
HSINK_7173DG [mil] "Aavid"
  round 115 hole 82: 1(-362.5,-173.23) 2(362.5,-173.23)
  silkscreen extent -375,-358 375,17, body extent -375,-358 375,12, height 900
IEC_HighVoltage_Medium [mil]
  silkscreen extent -217,-176 217,200
IEC_HotSurface_Medium [mil]
  silkscreen extent -217,-188 217,188
KBP [mm] "Diodes Inc Bridge Rectifier"
  rect 1.85x1.85 hole 1.35: 1(-5.715,0)
  round 1.85 hole 1.35: 2(-1.905,0) 3(1.905,0) 4(5.715,0)
  silkscreen extent -7.37,-2.23 7.38,1.42, body extent -7.37,-2.23 7.38,1.42, height 12.91
KCS0003B [mm] "Flange Mount, 3-Leads, Body 10.16x4.51mm, Pitch 2.54mm"
  rrect25% 1.6x1.6 hole 1: 1(0,2.54)
  round 1.6 hole 1: 2(0,0) 3(0,-2.54)
  silkscreen extent -1.71,-5.08 2.86,5.08, body extent -1.71,-5.09 2.86,5.08, height 18.63
Keystone5002 [mil] "For Keystone 500x miniature loop terminals"
  round 80 hole 40: 1(0,0)
  silkscreen extent -52,-52 52,52, body extent -49,-49 49,49, height 182
Keystone5010 [mil] "Keystone Multipurpose loops"
  round 87 hole 63: 1(0,0)
  silkscreen extent -70,-70 70,70, body extent -63,-63 63,62, height 319
Keystone5011 [mil] "Keystone Multipurpose loops"
  round 87 hole 63: 1(0,0)
  silkscreen extent -70,-70 70,70, body extent -63,-63 63,62, height 319
Keystone5125 [mil] "Keystone Multipurpose loops"
  round 87 hole 63: 1(0,0)
  silkscreen extent -70,-70 70,70, body extent -63,-63 63,62, height 319
Keystone5127 [mil] "Keystone Multipurpose loops"
  round 87 hole 63: 1(0,0)
  silkscreen extent -70,-70 70,70, body extent -63,-63 63,62, height 319
On-Shore_ED120_2DS [mm] "ONSHORE"
  rrect5% 2x2 hole 1.25: 1(-2.54,0)
  round 2 hole 1.25: 2(2.54,0)
  silkscreen extent -5.6,-4 5.12,5, body extent -5.78,-4 5.08,5, height 13
Renco_RTLI-1311 [mm] "TH, 12-Leads, Body 1450x1090mil"
  rrect50% 2.175x2.175 hole 1.45: 1(-15.24,11.43)
  round 2.175 hole 1.45: 2(-15.24,7.62) 3(-15.24,3.81) 4(-15.24,-3.81) 5(-15.24,-7.62) 6(-15.24,-11.43) 7(15.24,-11.43) 8(15.24,-7.62) 9(15.24,-3.81) 10(15.24,3.81) 11(15.24,7.62) 12(15.24,11.43)
  body extent -18.41,-13.84 18.42,13.84, height 23.11
SMA [mm] "Molded Diode, 2-Leads, Body 4.3x2.6mm, IPC Medium Density, based on OnSemi component dimensions and land pattern"
  rect 2x2 smd: 1(-2,0) 2(2,0)
  silkscreen extent -3.66,-1.57 2.79,1.57, body extent -2.6,-1.3 2.6,1.3, height 2.42
SMB [mil] "Molded Diode, 2-Leads, Body 5.4x3.6mm, IPC Medium Density, based on OnSemi component dimensions"
  rect 85x107.99 smd: 1(-87.01,0) 2(87.01,0)
  silkscreen extent -155,-82 125,82, body extent -106,-71 106,71, height 91
SMC [mil] "Molded Diode, 2-Leads, Body 6.9x5.8mm, IPC Medium Density, based on OnSemi component dimensions and land patterns"
  rect 110x150 smd: 1(-140.49,0) 2(140.49,0)
  silkscreen extent -221,-124 189,123, body extent -156,-116 156,116, height 91
SOD-123 [mm] "On Semi recommended land pattern"
  rect 0.915x1.22 smd: 1(-1.637,0) 2(1.637,0)
  silkscreen extent -2.74,-1.17 2.03,1.17, body extent -1.93,-0.9 1.93,0.9, height 1.35
SOD-123W [mm] "NXP recommended land pattern"
  rect 1.2x1.2 smd paste-0.05: 1(-1.4,0) 2(1.4,0)
  silkscreen extent -2.64,-1.14 1.68,1.14, body extent -1.85,-0.95 1.85,0.95, height 1.1
TO-220-3 [mm] "TH, 3-Leads, Body 10.2235x4.3815mm, Pitch 2.54mm"
  rrect50% 1.6x1.6 hole 1.1: 1(-2.54,0)
  round 1.6 hole 1.1: 2(0,0) 3(2.54,0)
  silkscreen extent -5.3,-1.7 5.3,2.9, body extent -5.27,-1.7 5.28,2.9, height 22.15
TO-220AB [mil] "Copied from Altium's version of TO3B"
  rrect25% 76x118.11 hole 50: 1(-100,0)
  oval 76x118.11 hole 50: 2(0,0) 3(100,0)
  silkscreen extent -221,-59 221,126, body extent -221,-59 221,126, height 765
WCAP-FTX2_1800x600x1200 [mm] "TH, 2-Leads, Body 18x6mm, Lead Spacing 15mm"
  round 1.6 hole 1.1: 1(-7.5,0) 2(7.5,0)
  silkscreen extent -9.25,-3.25 9.25,3.25, body extent -9.25,-3.25 9.25,3.25, height 12.5
WE-CMBNC_XS [mm] "TH, 4-Leads, Body 14x7.5mm"
  rect 1.6x1.6 hole 1.1: 1(-2.25,5)
  round 1.6 hole 1.1: 2(-2.25,-5) 3(2.25,-5) 4(2.25,5)
  silkscreen extent -4.1,-6.5 3.75,6.5, body extent -3.75,-6.5 3.75,6.5, height 14.6
WE-FI_1350x700 [mm] "TH, 2-Leads, Dia 13.5mm"
  round 1.25 hole 0.75: 1(-3,0) 2(3,0)
  silkscreen extent -3.25,-6.75 3.25,6.75, body extent -3.25,-6.75 3.25,6.75, height 13.32
WE-HCC_1090 [mm] "WERTH"
  rect 2.3x3.6 smd: 1(-4.6,0) 2(4.6,0)
  silkscreen extent -5.7,-5.3 5.7,5.3, body extent -5.12,-5 5.13,5, height 9.87
"WE-HCF Round_2920" [mm] "SMT High Current Inductor, 2-Leads, body 28x25mm"
  rrect1% 8.5x8 smd: 1(-8.5,0) 2(8.5,0)
  body extent -11.55,-13.65 11.55,13.65, height 20
WE-TPC-XLH2 [mm] "Wurth Elektronik recommended land pattern, 2008-04-11"
  rect 1.8x4.6 smd: 1(-4.5,0) 2(4.5,0)
  silkscreen extent -5.15,-5.15 5.15,5.15, body extent -5.15,-5.15 5.15,5.15, height 3.1
WEEE_Minimum [mil] "WEEElie bin"
  silkscreen extent -95,-172 99,104
Wurth_691214310002 [mm] "WE"
  rect 2x2 hole 1.3: 1(-1.905,0)
  round 2 hole 1.3: 2(1.905,0)
  silkscreen extent -4.12,-3.5 3.9,3.9, body extent -4.12,-3.5 3.9,3.9, height 8.52

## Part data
C1 C2 C6: library part CMP-0009076-1, "CAP, CERM, 0.1 uF, 630 V, +/- 10%, X7R, 1210", Cap_Case=1210, Manufacturer=Kemet, Supplier Part Number 1=399-13490-1-ND, TempCo=X7R, Tolerance_%=10%, Value1=Unknown, Value2=630V, ValueDisplayed=0.1uF
C3 C4 C5 C22: library part CMP-0078361-1, "CAP, AL, 47 µF, 450 V, +/- 20%, TH", Cap_Case=12.5x35mm, Manufacturer=Rubycon, Supplier Part Number 1=1189-1361-ND, Tolerance_%=20%, Value2=450V, ValueDisplayed=47µF
C7: library part CMP-0008969-2, "CAP, CERM, 4.7 uF, 50 V, +/- 10%, X7R, 1206", Cap_Case=2220, Manufacturer=MuRata, Supplier Part Number 1=24R6347, TempCo=X7R, Tolerance_%=10%, Value1=Unknown, Value2=50V, ValueDisplayed=4.7uF
C8: library part CMP-0008805-2, "CAP, CERM, 22 uF, 25 V, +/- 20%, X7R, 1206_190", Cap_Case=1206, Manufacturer="Taiyo Yuden", Supplier Part Number 1=587-4319-1-ND, TempCo=X7R, Tolerance_%=20%, Value1=Unknown, Value2=16V, ValueDisplayed=22uF
C9 C32: library part CMP-0007446-5, "CAP, CERM, 270 pF, 50 V, +/- 10%, X7R, 0603", Cap_Case=0603, Manufacturer=MuRata, Supplier Part Number 1=490-1485-1-ND, TempCo=X7R, Tolerance_%=10%, Value1=Unknown, Value2=50V, ValueDisplayed=270pF
C10: library part CMP-0007433-4, "CAP, CERM, 0.01 uF, 50 V, +/- 10%, X7R, 0603", Cap_Case=0603, Manufacturer=MuRata, Supplier Part Number 1=490-1512-1-ND, TempCo=X7R, Tolerance_%=10%, Value1=Unknown, Value2=50V, ValueDisplayed=0.01uF
C11: library part CMP-0007414-4, "CAP, CERM, 2200 pF, 25 V, +/- 10%, X7R, 0603", Cap_Case=0603, Manufacturer=MuRata, Supplier Part Number 1=GRM188R71E222KA01D-ND, TempCo=X7R, Tolerance_%=10%, Value1=Unknown, Value2=25V, ValueDisplayed=2200pF
C12: library part CMP-0007424-4, "CAP, CERM, 0.47 uF, 25 V, +/- 10%, X7R, 0603", Cap_Case=0603, Manufacturer=MuRata, Supplier Part Number 1=490-3291-1-ND, TempCo=X7R, Tolerance_%=10%, Value1=Unknown, Value2=25V, ValueDisplayed=0.47uF
C13: library part CMP-0012314-3, "CAP, Film, 0.1 uF, 275 V, +/- 10%, TH", Cap_Case=18x6x12mm, Manufacturer="Wurth Elektronik", Supplier Part Number 1=732-5898-ND, Tolerance_%=10%, Value1=Unknown, Value2=275V, ValueDisplayed=0.1uF
C14 C15 C16 C17 C18 C19: library part CMP-0087257-2, "CAP ALUM 680UF 20% 35V THRU HOLE", Manufacturer="Wurth Electronics", Tolerance_%=20%, ValueDisplayed=680uF
C20 C36 C37: library part CMP-0009190-2, "CAP, CERM, 10 uF, 25 V, +/- 10%, X7R, 1210", Cap_Case=1210, Manufacturer=MuRata, Supplier Part Number 1=490-1867-1-ND, TempCo=X7R, Tolerance_%=10%, Value1=Unknown, Value2=25V, ValueDisplayed=10uF
C21 C34 C35: library part CMP-0006659-2, "CAP, CERM, 0.1 uF, 25 V, +/- 10%, X7R, 0402", Cap_Case=0402, Manufacturer=MuRata, Supplier Part Number 1=490-10698-1-ND, TempCo=X7R, Tolerance_%=10%, Value1=Unknown, Value2=25V, ValueDisplayed=0.1uF
C23: library part CMP-0009060-2, "CAP, CERM, 0.047 uF, 500 V, +/- 10%, X7R, 1206", Cap_Case=1206, Manufacturer=Vishay-Vitramon, Supplier Part Number 1=720-1033-1-ND, TempCo=X7R, Tolerance_%=10%, Value1=Unknown, Value2=500V, ValueDisplayed=0.047uF
C24: library part CMP-0008482-2, "CAP, CERM, 1000 pF, 100 V, +/- 5%, X7R, 1206", Cap_Case=1206, Manufacturer=AVX, Supplier Part Number 1=478-3782-1-ND, TempCo=X7R, Tolerance_%=5%, Value1="0.427 ohm", Value2=100V, ValueDisplayed=1000pF
C25: library part CMP-0007475-4, "CAP, CERM, 2200 pF, 100 V, +/- 10%, X7R, 0603", Cap_Case=0603, Manufacturer=MuRata, Supplier Part Number 1=490-1478-1-ND, TempCo=X7R, Tolerance_%=10%, Value1=Unknown, Value2=100V, ValueDisplayed=2200pF
C26: library part CMP-0007770-2, "CAP, CERM, 2.2 uF, 16 V, +/- 10%, X7R, 0805", Cap_Case=0805, Manufacturer=Kemet, Supplier Part Number 1=399-3523-1-ND, TempCo=X7R, Tolerance_%=10%, Value1="0.008 ohm", Value2=16V, ValueDisplayed=2.2uF
C27: library part CMP-0086249-1, "CAP, CERM, 1 µF, 50 V,+/- 10%, X7R, AEC-Q200 Grade 1, 0805", Cap_Case=0805, Manufacturer=MuRata, TempCo=X7R, Tolerance_%=10%, Value2=50V, ValueDisplayed=1µF
C28: library part CMP-0085950-1, "CAP, CERM, 10 µF, 50 V,+/- 10%, X7R, AEC-Q200 Grade 1, 1206", Cap_Case=1206, Manufacturer=TDK, TempCo=X7R, Tolerance_%=10%, Value2=50V, ValueDisplayed=10µF
C29: library part CMP-0007039-5, "CAP, CERM, 0.1 uF, 25 V, +/- 10%, X7R, 0603", Cap_Case=0603, Manufacturer=TDK, Supplier Part Number 1=445-1316-1-ND, TempCo=X7R, Tolerance_%=10%, Value1=Unknown, Value2=25V, ValueDisplayed=0.1uF
C30: library part CMP-0007397-4, "CAP, CERM, 0.047 uF, 16 V, +/- 10%, X7R, 0603", Cap_Case=0603, Manufacturer=MuRata, Supplier Part Number 1=490-1529-1-ND, TempCo=X7R, Tolerance_%=10%, Value1=Unknown, Value2=16V, ValueDisplayed=0.047uF
C31: library part CMP-0007410-5, "CAP, CERM, 0.015 uF, 25 V, +/- 10%, X7R, 0603", Cap_Case=0603, Manufacturer=MuRata, Supplier Part Number 1=81-GRM39X153K25D, TempCo=X7R, Tolerance_%=10%, Value1=Unknown, Value2=25V, ValueDisplayed=0.015uF
C33: library part CMP-0078358-1, "CAP, CERM, 2200 pF, X1 400 VAC/Y1 400 VAC, +/- 20%, Y5V, D9xL13mm", Cap_Case=9x13mm, Manufacturer=Kemet, Supplier Part Number 1=399-9487-1-ND, TempCo=Y5V, Tolerance_%=20%, ValueDisplayed=2200pF
C38 C39 C40 C41: library part CMP-0008286-2, "CAP, CERM, 22 uF, 10 V, +/- 20%, X5R, 0805", Cap_Case=0805, Manufacturer=MuRata, Supplier Part Number 1=490-10746-1-ND, TempCo=X5R, Tolerance_%=20%, Value1=Unknown, Value2=10V, ValueDisplayed=22uF
C42: library part CMP-0006251-1, "CAP, CERM, 68 pF, 50 V, +/- 5%, C0G/NP0, 0402", Cap_Case=0402, Manufacturer=TDK, Supplier Part Number 1=445-1245-1-ND, TempCo=C0G/NP0, Tolerance_%=5%, Value1=Unknown, Value2=50V, ValueDisplayed=68pF
C43: library part CMP-0006242-1, "CAP, CERM, 33 pF, 50 V, +/- 5%, C0G/NP0, 0402", Cap_Case=0402, Manufacturer=Kemet, Supplier Part Number 1=399-1017-1-ND, TempCo=C0G/NP0, Tolerance_%=5%, Value1=Unknown, Value2=50V, ValueDisplayed=33pF
D1: library part CMP-0085336-1, "Diode, Ultrafast, 400 V, 8 A, TO-220AB", Manufacturer="ON Semiconductor", Value1=8A, Value2=16V
D2: library part CMP-0029027-2, "Diode, Ultrafast, 400 V, 1 A, SMB", Manufacturer="Diodes Inc.", Value1=1A, Value2=1.25V
D3: library part CMP-0085423-1, "Diode, TVS, Uni, 13 V, 21.5 Vc, 1500 W, 73 A, SMC", Manufacturer=STMicroelectronics, Value1=21.5V
D4: library part CMP-0005738-4, "Diode, Zener, 56 V, 500 mW, AEC-Q101, SOD-123", Manufacturer="ON Semiconductor", Power_W=500mW, Value1=0.5W
D5: library part CMP-0005786-3, "Diode, Zener, 5.1 V, 500 mW, SOD-123", Manufacturer="ON Semiconductor", Power_W=500mW, Value1=0.5W
D6: library part CMP-0029224-3, "Diode, Switching-Bridge, 600 V, 1.5 A, TH", Manufacturer="Diodes Inc.", Value1=1.5A, Value2=1.1V
D7: library part CMP-0065113-3, "Diode, TVS, Uni, 200 V, 324 Vc, SMC", Manufacturer=Littelfuse, Value1=1500W
D8: library part CMP-0076882-2, "Diode, Ultrafast, 1000 V, 1 A, SMA", Manufacturer="Diodes Inc.", Value1=1A, Value2=1.7V
D9: library part CMP-0028782-2, "Diode, Schottky, 100 V, 1 A, AEC-Q101, SOD-123W", Manufacturer=Nexperia, Value1=1A, Value2=0.77V
F1: library part CMP-0003560-2, "Fuse, 6.3 A, 250VAC/VDC, TH", Irating_A=6.3A, Manufacturer=Littelfuse, Supplier Part Number 1=WK6336CT-ND
H1 H2: library part CMP-0086466-3, "Heat Sink TO-220 Aluminum 8.0W @ 70°C Board Level, Vertical", Manufacturer="Aavid Thermalloy"
H3: library part CMP-0004019-1, "Heat Sink, TO-220 Vertical", Manufacturer=Aavid, Supplier Part Number 1=HS415-ND
J1: library part CMP-0074910-1, "Terminal Block, 5.08 mm, 2x1, Brass, TH", Color=Blue, Current_A=15A, Manufacturer="On-Shore Technology", Supplier Part Number 1=ED1609-ND, Voltage_V=300V
J2: library part CMP-0074930-1, "AC Receptacle, 2.5A, R/A, TH", Manufacturer="Qualtek Electronics Corporation", Supplier Part Number 1=Q273-ND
